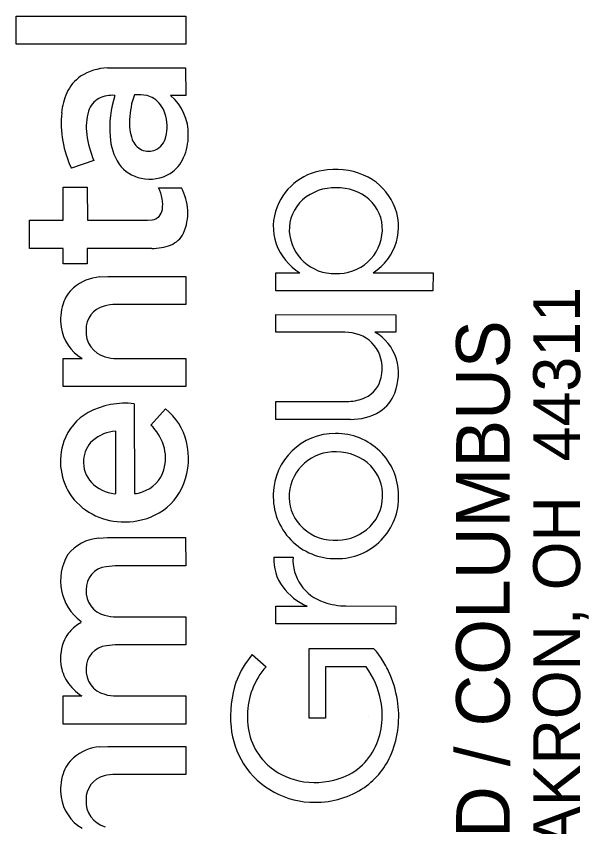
# Model space of a CAD drawing. Extents: x -1.6 to 34, y 0 to 22.
# Drawn here: x 32.376 to 32.984, y 3.882 to 4.744 of the extents above; entities that cross this region are included whole.
import ezdxf

# ---------------------------------------------------------------- set-up
doc = ezdxf.new("R2010")
doc.units = 0
doc.layers.add('SH_Data', color=7, linetype='Continuous')

msp = doc.modelspace()

# ---------------------------------------------------------------- linework, layer by layer
at = {"layer": 'SH_Data'}
for p, q in [((32.37557, 4.71411), (32.37557, 4.74397)), ((32.37557, 4.74397), (32.55571, 4.74397)), ((32.55571, 4.74397), (32.55571, 4.71411)), ((32.55571, 4.71411), (32.37557, 4.71411)), ((32.47265, 4.68899), (32.55553, 4.68918)), ((32.55553, 4.68918), (32.55571, 4.65956)), ((32.55571, 4.65956), (32.53971, 4.65956)), ((32.45818, 4.59045), (32.43431, 4.58233)), ((32.42542, 4.52705), (32.42548, 4.56209)), ((32.42548, 4.56209), (32.45108, 4.56209)), ((32.45108, 4.56209), (32.45117, 4.52705)), ((32.52695, 4.56159), (32.5511, 4.56159)), ((32.38964, 4.52701), (32.42542, 4.52705)), ((32.38964, 4.49719), (32.38964, 4.52701)), ((32.45117, 4.52705), (32.51498, 4.52705)), ((32.51498, 4.52705), (32.52005, 4.52749)), ((32.42542, 4.49717), (32.38964, 4.49719)), ((32.42542, 4.48067), (32.42542, 4.49717)), ((32.51969, 4.49718), (32.45108, 4.49715)), ((32.45108, 4.49715), (32.45108, 4.48066)), ((32.45108, 4.48066), (32.42542, 4.48067)), ((32.46439, 4.46686), (32.47289, 4.46732)), ((32.47289, 4.46732), (32.55571, 4.46732)), ((32.55571, 4.46732), (32.55571, 4.43753)), ((32.65152, 4.47113), (32.67709, 4.47115)), ((32.65152, 4.45215), (32.65152, 4.47113)), ((32.75491, 4.47132), (32.81858, 4.47108)), ((32.81858, 4.47108), (32.81843, 4.45215)), ((32.81843, 4.45215), (32.65152, 4.45215)), ((32.55571, 4.43753), (32.4814, 4.43746)), ((32.65152, 4.40801), (32.65153, 4.42672)), ((32.65153, 4.42672), (32.7791, 4.42664)), ((32.7791, 4.42664), (32.77908, 4.40796)), ((32.7249, 4.40796), (32.65152, 4.40801)), ((32.7328, 4.40727), (32.7249, 4.40796)), ((32.77908, 4.40796), (32.75689, 4.40796)), ((32.42542, 4.38016), (32.44552, 4.38021)), ((32.42542, 4.35035), (32.42542, 4.38016)), ((32.48222, 4.38021), (32.55569, 4.38021)), ((32.55569, 4.38021), (32.55571, 4.35045)), ((32.55571, 4.35045), (32.42542, 4.35035)), ((32.65154, 4.33443), (32.72905, 4.3345)), ((32.65165, 4.31543), (32.65154, 4.33443)), ((32.50108, 4.33209), (32.50118, 4.23657)), ((32.51882, 4.30927), (32.53422, 4.32662)), ((32.73073, 4.31543), (32.65165, 4.31543)), ((32.48144, 4.23644), (32.48144, 4.30296)), ((32.48016, 4.23628), (32.48144, 4.23644)), ((32.46329, 4.18915), (32.47259, 4.18968)), ((32.47259, 4.18968), (32.55557, 4.18968)), ((32.55557, 4.18968), (32.55571, 4.15982)), ((32.64932, 4.16907), (32.66978, 4.16907)), ((32.48058, 4.15981), (32.47102, 4.15881)), ((32.55571, 4.15982), (32.48058, 4.15981)), ((32.65152, 4.11699), (32.68476, 4.117)), ((32.65152, 4.098), (32.65152, 4.11699)), ((32.72605, 4.11703), (32.7791, 4.11696)), ((32.7791, 4.11696), (32.77903, 4.098)), ((32.48218, 4.10553), (32.55571, 4.10548)), ((32.55571, 4.10548), (32.55571, 4.07568)), ((32.44443, 4.09922), (32.44455, 4.10072)), ((32.77903, 4.098), (32.65152, 4.098)), ((32.4809, 4.07567), (32.47143, 4.07474)), ((32.55571, 4.07568), (32.4809, 4.07567)), ((32.6868, 4.07185), (32.75516, 4.07192)), ((32.6868, 3.99778), (32.6868, 4.07185)), ((32.62636, 4.06548), (32.64114, 4.05241)), ((32.70448, 4.05241), (32.70432, 3.99775)), ((32.74737, 4.05227), (32.70448, 4.05241)), ((32.42542, 3.99152), (32.42545, 4.02138)), ((32.42545, 4.02138), (32.44515, 4.02138)), ((32.48206, 4.02138), (32.55571, 4.02136)), ((32.55571, 4.02136), (32.55571, 3.99156)), ((32.75, 4), (32.75, 4)), ((32.55571, 3.99156), (32.42542, 3.99152)), ((32.70432, 3.99775), (32.6868, 3.99778)), ((32.46439, 3.96736), (32.47289, 3.96783)), ((32.47289, 3.96783), (32.55571, 3.96783)), ((32.55571, 3.96783), (32.55571, 3.93804)), ((32.55571, 3.93804), (32.4814, 3.93796))]:
    msp.add_line(p, q, dxfattribs=at)
msp.add_lwpolyline([(32.37557, 4.71411), (32.37557, 4.74397), (32.55571, 4.74397), (32.55571, 4.71411)], close=True, dxfattribs=at)
for points in [[(32.47265, 4.68899), (32.55553, 4.68918), (32.55571, 4.65956)], [(32.55571, 4.65956), (32.53971, 4.65956)], [(32.45818, 4.59045), (32.43431, 4.58233)], [(32.51969, 4.49718), (32.45108, 4.49715), (32.45108, 4.48066), (32.42542, 4.48067), (32.42542, 4.49717), (32.38964, 4.49719), (32.38964, 4.52701), (32.42542, 4.52705), (32.42548, 4.56209), (32.45108, 4.56209), (32.45117, 4.52705), (32.51498, 4.52705), (32.52005, 4.52749)], [(32.52695, 4.56159), (32.5511, 4.56159)], [(32.46439, 4.46686), (32.47289, 4.46732), (32.55571, 4.46732), (32.55571, 4.43753), (32.4814, 4.43746)], [(32.75491, 4.47132), (32.81858, 4.47108), (32.81843, 4.45215), (32.65152, 4.45215)], [(32.65152, 4.45215), (32.65152, 4.47113), (32.67709, 4.47115)], [(32.7328, 4.40727), (32.7249, 4.40796), (32.65152, 4.40801), (32.65153, 4.42672), (32.7791, 4.42664), (32.77908, 4.40796), (32.75689, 4.40796)], [(32.42542, 4.35035), (32.42542, 4.38016), (32.44552, 4.38021)], [(32.48222, 4.38021), (32.55569, 4.38021), (32.55571, 4.35045), (32.42542, 4.35035)], [(32.73073, 4.31543), (32.65165, 4.31543), (32.65154, 4.33443), (32.72905, 4.3345)], [(32.50108, 4.33209), (32.50118, 4.23657)], [(32.51882, 4.30927), (32.53422, 4.32662)], [(32.48016, 4.23628), (32.48144, 4.23644), (32.48144, 4.30296)], [(32.46329, 4.18915), (32.47259, 4.18968), (32.55557, 4.18968), (32.55571, 4.15982), (32.48058, 4.15981), (32.47102, 4.15881)], [(32.64932, 4.16907), (32.66978, 4.16907)], [(32.72605, 4.11703), (32.7791, 4.11696), (32.77903, 4.098), (32.65152, 4.098)], [(32.65152, 4.098), (32.65152, 4.11699), (32.68476, 4.117)], [(32.48218, 4.10553), (32.55571, 4.10548), (32.55571, 4.07568), (32.4809, 4.07567), (32.47143, 4.07474)], [(32.44443, 4.09922), (32.44455, 4.10072)], [(32.74737, 4.05227), (32.70448, 4.05241), (32.70432, 3.99775), (32.6868, 3.99778), (32.6868, 4.07185), (32.75516, 4.07192)], [(32.62636, 4.06548), (32.64114, 4.05241)], [(32.42542, 3.99152), (32.42545, 4.02138), (32.44515, 4.02138)], [(32.48206, 4.02138), (32.55571, 4.02136), (32.55571, 3.99156), (32.42542, 3.99152)], [(32.46439, 3.96736), (32.47289, 3.96783), (32.55571, 3.96783), (32.55571, 3.93804), (32.4814, 3.93796)]]:
    msp.add_lwpolyline(points, dxfattribs=at)
for centre, radius, start, end in [((32.47452, 4.63256), 0.05646, 91.89422, 122.63175), ((32.47452, 4.63256), 0.05646, 91.89422, 122.63175), ((32.46847, 4.64467), 0.04302, 124.53704, 155.65938), ((32.46847, 4.64467), 0.04302, 124.53704, 155.65938), ((32.48824, 4.63612), 0.06457, 155.9764, 175.31491), ((32.48824, 4.63612), 0.06457, 155.9764, 175.31491), ((32.47525, 4.6356), 0.024, 119.42515, 161.66285), ((32.47525, 4.6356), 0.024, 119.42515, 161.66285), ((32.47786, 4.62778), 0.03213, 85.38017, 116.62224), ((32.47786, 4.62778), 0.03213, 85.38017, 116.62224), ((32.58787, 4.62508), 0.1129, 162.08213, 184.52847), ((32.58787, 4.62508), 0.1129, 162.08213, 184.52847), ((32.58013, 4.63131), 0.08411, 159.83657, 178.03621), ((32.58013, 4.63131), 0.08411, 159.83657, 178.03621), ((32.50509, 4.60743), 0.05302, 79.66963, 94.23216), ((32.50509, 4.60743), 0.05302, 79.66963, 94.23216), ((32.50892, 4.63643), 0.02384, 56.89129, 76.21489), ((32.50892, 4.63643), 0.02384, 56.89129, 76.21489), ((32.5052, 4.63184), 0.02973, 17.59837, 55.72819), ((32.5052, 4.63184), 0.02973, 17.59837, 55.72819), ((32.50551, 4.61914), 0.05295, 358.07459, 49.76196), ((32.50551, 4.61914), 0.05295, 358.07459, 49.76196), ((32.53639, 4.63078), 0.113, 174.61011, 205.38987), ((32.53639, 4.63078), 0.113, 174.61011, 205.38987), ((32.50758, 4.62645), 0.05758, 163.13694, 188.16749), ((32.50758, 4.62645), 0.05758, 163.13694, 188.16749), ((32.4916, 4.6264), 0.04435, 345.94084, 18.99188), ((32.4916, 4.6264), 0.04435, 345.94084, 18.99188), ((32.54655, 4.6303), 0.05063, 175.59026, 199.88569), ((32.54655, 4.6303), 0.05063, 175.59026, 199.88569), ((32.54725, 4.62973), 0.09735, 186.75982, 203.79807), ((32.54725, 4.62973), 0.09735, 186.75982, 203.79807), ((32.53279, 4.61874), 0.05752, 182.56764, 213.71437), ((32.53279, 4.61874), 0.05752, 182.56764, 213.71437), ((32.51642, 4.61886), 0.01841, 198.28436, 293.30806), ((32.51642, 4.61886), 0.01841, 198.28436, 293.30806), ((32.51521, 4.61994), 0.01989, 295.28829, 347.46387), ((32.51521, 4.61994), 0.01989, 295.28829, 347.46387), ((32.50187, 4.61678), 0.05657, 336.01604, 0.59505), ((32.50187, 4.61678), 0.05657, 336.01604, 0.59505), ((32.51752, 4.60969), 0.03938, 303.44357, 336.18), ((32.51752, 4.60969), 0.03938, 303.44357, 336.18), ((32.51487, 4.60782), 0.03656, 215.06685, 259.81327), ((32.51487, 4.60782), 0.03656, 215.06685, 259.81327), ((32.51753, 4.6131), 0.04227, 257.52557, 300.88195), ((32.51753, 4.6131), 0.04227, 257.52557, 300.88195), ((32.71081, 4.51825), 0.06243, 93.98662, 158.31194), ((32.71081, 4.51825), 0.06243, 93.98662, 158.31194), ((32.71557, 4.5065), 0.07459, 62.68889, 97.01346), ((32.71557, 4.5065), 0.07459, 62.68889, 97.01346), ((32.72123, 4.51914), 0.06076, 25.06574, 61.96022), ((32.72123, 4.51914), 0.06076, 25.06574, 61.96022), ((32.48625, 4.54199), 0.04518, 10.15449, 25.72303), ((32.48625, 4.54199), 0.04518, 10.15449, 25.72303), ((32.50302, 4.53506), 0.05491, 336.58903, 28.89913), ((32.50302, 4.53506), 0.05491, 336.58903, 28.89913), ((32.71379, 4.51017), 0.05134, 87.89653, 131.18123), ((32.71379, 4.51017), 0.05134, 87.89653, 131.18123), ((32.7175, 4.51023), 0.05127, 49.90886, 92.03625), ((32.7175, 4.51023), 0.05127, 49.90886, 92.03625), ((32.49573, 4.54365), 0.03556, 351.91398, 10.20594), ((32.49573, 4.54365), 0.03556, 351.91398, 10.20594), ((32.70695, 4.52016), 0.05815, 158.65601, 198.17101), ((32.70695, 4.52016), 0.05815, 158.65601, 198.17101), ((32.7092, 4.51674), 0.04338, 132.32887, 182.09489), ((32.7092, 4.51674), 0.04338, 132.32887, 182.09489), ((32.72154, 4.51733), 0.04327, 358.04871, 47.94467), ((32.72154, 4.51733), 0.04327, 358.04871, 47.94467), ((32.7245, 4.52004), 0.05743, 301.97764, 25.64176), ((32.7245, 4.52004), 0.05743, 301.97764, 25.64176), ((32.51837, 4.54001), 0.01263, 277.61423, 353.79181), ((32.51837, 4.54001), 0.01263, 277.61423, 353.79181), ((32.71352, 4.51815), 0.04776, 183.59741, 271.7045), ((32.71352, 4.51815), 0.04776, 183.59741, 271.7045), ((32.71717, 4.51801), 0.04766, 267.31494, 357.4019), ((32.71717, 4.51801), 0.04766, 267.31494, 357.4019), ((32.52913, 4.52612), 0.02749, 292.68889, 332.05977), ((32.52913, 4.52612), 0.02749, 292.68889, 332.05977), ((32.52088, 4.54856), 0.05139, 268.67266, 291.52354), ((32.52088, 4.54856), 0.05139, 268.67266, 291.52354), ((32.7103, 4.52433), 0.0627, 200.83985, 238.01619), ((32.7103, 4.52433), 0.0627, 200.83985, 238.01619), ((32.46871, 4.41716), 0.04988, 94.97056, 130.22484), ((32.46871, 4.41716), 0.04988, 94.97056, 130.22484), ((32.46348, 4.42551), 0.04016, 132.22383, 161.68229), ((32.46348, 4.42551), 0.04016, 132.22383, 161.68229), ((32.47872, 4.42108), 0.05602, 162.27398, 187.79173), ((32.47872, 4.42108), 0.05602, 162.27398, 187.79173), ((32.48108, 4.39145), 0.04601, 89.60515, 105.33026), ((32.48108, 4.39145), 0.04601, 89.60515, 105.33026), ((32.47482, 4.41155), 0.02498, 103.68683, 182.21395), ((32.47482, 4.41155), 0.02498, 103.68683, 182.21395), ((32.47027, 4.4209), 0.04763, 188.96462, 238.69865), ((32.47027, 4.4209), 0.04763, 188.96462, 238.69865), ((32.47735, 4.40846), 0.02757, 175.58441, 255.13816), ((32.47735, 4.40846), 0.02757, 175.58441, 255.13816), ((32.72711, 4.36998), 0.03772, 33.50082, 81.32954), ((32.72711, 4.36998), 0.03772, 33.50082, 81.32954), ((32.73239, 4.36485), 0.04959, 17.62209, 60.38974), ((32.73239, 4.36485), 0.04959, 17.62209, 60.38974), ((32.72414, 4.3695), 0.04048, 346.56179, 31.75389), ((32.72414, 4.3695), 0.04048, 346.56179, 31.75389), ((32.48183, 4.42235), 0.04215, 254.08913, 270.52838), ((32.48183, 4.42235), 0.04215, 254.08913, 270.52838), ((32.72343, 4.36415), 0.05838, 339.16197, 15.61485), ((32.72343, 4.36415), 0.05838, 339.16197, 15.61485), ((32.73371, 4.36616), 0.03042, 294.63214, 348.48625), ((32.73371, 4.36616), 0.03042, 294.63214, 348.48625), ((32.739, 4.35901), 0.04201, 303.10391, 338.15613), ((32.739, 4.35901), 0.04201, 303.10391, 338.15613), ((32.72747, 4.38081), 0.04633, 271.95199, 294.08943), ((32.72747, 4.38081), 0.04633, 271.95199, 294.08943), ((32.49176, 4.24874), 0.08387, 83.62118, 118.28448), ((32.49176, 4.24874), 0.08387, 83.62118, 118.28448), ((32.49399, 4.2763), 0.06443, 13.53275, 51.36266), ((32.49399, 4.2763), 0.06443, 13.53275, 51.36266), ((32.47894, 4.27368), 0.05583, 118.82935, 160.62242), ((32.47894, 4.27368), 0.05583, 118.82935, 160.62242), ((32.7321, 4.37256), 0.05715, 268.62699, 301.47779), ((32.7321, 4.37256), 0.05715, 268.62699, 301.47779), ((32.48033, 4.27018), 0.05485, 19.0387, 45.44322), ((32.48033, 4.27018), 0.05485, 19.0387, 45.44322), ((32.4844, 4.26071), 0.04236, 94.01311, 130.88062), ((32.4844, 4.26071), 0.04236, 94.01311, 130.88062), ((32.71435, 4.23484), 0.06552, 89.48213, 178.77752), ((32.71435, 4.23484), 0.06552, 89.48213, 178.77752), ((32.71582, 4.23414), 0.06623, 0.42265, 90.7613), ((32.71582, 4.23414), 0.06623, 0.42265, 90.7613), ((32.48697, 4.27074), 0.06438, 160.52138, 215.78155), ((32.48697, 4.27074), 0.06438, 160.52138, 215.78155), ((32.47703, 4.2709), 0.02985, 132.98553, 177.1802), ((32.47703, 4.2709), 0.02985, 132.98553, 177.1802), ((32.48289, 4.27384), 0.0758, 339.35431, 13.37708), ((32.48289, 4.27384), 0.0758, 339.35431, 13.37708), ((32.48724, 4.27433), 0.04701, 344.60723, 17.00675), ((32.48724, 4.27433), 0.04701, 344.60723, 17.00675), ((32.71397, 4.23244), 0.04846, 87.68827, 175.01696), ((32.71397, 4.23244), 0.04846, 87.68827, 175.01696), ((32.71659, 4.23036), 0.05052, 44.91202, 90.75914), ((32.71659, 4.23036), 0.05052, 44.91202, 90.75914), ((32.47824, 4.26966), 0.03114, 175.00138, 223.2876), ((32.47824, 4.26966), 0.03114, 175.00138, 223.2876), ((32.71955, 4.23452), 0.04549, 358.32279, 43.83486), ((32.71955, 4.23452), 0.04549, 358.32279, 43.83486), ((32.49895, 4.27177), 0.03504, 288.01084, 343.55364), ((32.49895, 4.27177), 0.03504, 288.01084, 343.55364), ((32.48546, 4.27826), 0.04232, 225.06454, 262.79701), ((32.48546, 4.27826), 0.04232, 225.06454, 262.79701), ((32.49548, 4.26982), 0.0626, 300.94393, 338.73223), ((32.49548, 4.26982), 0.0626, 300.94393, 338.73223), ((32.48908, 4.27516), 0.06872, 217.74341, 271.65606), ((32.48908, 4.27516), 0.06872, 217.74341, 271.65606), ((32.50129, 4.25678), 0.02021, 269.70042, 294.87295), ((32.50129, 4.25678), 0.02021, 269.70042, 294.87295), ((32.71483, 4.2334), 0.06606, 177.53728, 270.94524), ((32.71483, 4.2334), 0.06606, 177.53728, 270.94524), ((32.71085, 4.23311), 0.0453, 175.51467, 221.42047), ((32.71085, 4.23311), 0.0453, 175.51467, 221.42047), ((32.71671, 4.23271), 0.06536, 269.30834, 1.67905), ((32.71671, 4.23271), 0.06536, 269.30834, 1.67905), ((32.71931, 4.23374), 0.04572, 308.90382, 359.30947), ((32.71931, 4.23374), 0.04572, 308.90382, 359.30947), ((32.49204, 4.27702), 0.07055, 269.20529, 300.33566), ((32.49204, 4.27702), 0.07055, 269.20529, 300.33566), ((32.71399, 4.23734), 0.05046, 222.66255, 268.37331), ((32.71399, 4.23734), 0.05046, 222.66255, 268.37331), ((32.71567, 4.23859), 0.05178, 266.55312, 308.67253), ((32.71567, 4.23859), 0.05178, 266.55312, 308.67253), ((32.46638, 4.14404), 0.04521, 93.91118, 142.30723), ((32.46638, 4.14404), 0.04521, 93.91118, 142.30723), ((32.47585, 4.14373), 0.05319, 148.28793, 233.9556), ((32.47585, 4.14373), 0.05319, 148.28793, 233.9556), ((32.69878, 4.16662), 0.04952, 177.16211, 216.28024), ((32.69878, 4.16662), 0.04952, 177.16211, 216.28024), ((32.71735, 4.16638), 0.04764, 176.76988, 252.15044), ((32.71735, 4.16638), 0.04764, 176.76988, 252.15044), ((32.47384, 4.13499), 0.02399, 96.75763, 181.6251), ((32.47384, 4.13499), 0.02399, 96.75763, 181.6251), ((32.70975, 4.17555), 0.06366, 216.91526, 246.88619), ((32.70975, 4.17555), 0.06366, 216.91526, 246.88619), ((32.47577, 4.13241), 0.02597, 175.81573, 256.16716), ((32.47577, 4.13241), 0.02597, 175.81573, 256.16716), ((32.7269, 4.19175), 0.07473, 251.13884, 269.34694), ((32.7269, 4.19175), 0.07473, 251.13884, 269.34694), ((32.4817, 4.15053), 0.04501, 254.34629, 270.61033), ((32.4817, 4.15053), 0.04501, 254.34629, 270.61033), ((32.4638, 4.06267), 0.04137, 117.91625, 139.24296), ((32.4638, 4.06267), 0.04137, 117.91625, 139.24296), ((32.46194, 4.06452), 0.03875, 139.52447, 154.84698), ((32.46194, 4.06452), 0.03875, 139.52447, 154.84698), ((32.47144, 4.0612), 0.04877, 156.06382, 187.3493), ((32.47144, 4.0612), 0.04877, 156.06382, 187.3493), ((32.47421, 4.05056), 0.02434, 96.5532, 179.94902), ((32.47421, 4.05056), 0.02434, 96.5532, 179.94902), ((32.72498, 4.03937), 0.04438, 30.98913, 47.16099), ((32.72498, 4.03937), 0.04438, 30.98913, 47.16099), ((32.70163, 4.00187), 0.09855, 139.79476, 159.13696), ((32.70163, 4.00187), 0.09855, 139.79476, 159.13696), ((32.67091, 4.00018), 0.11106, 25.30315, 33.96179), ((32.67091, 4.00018), 0.11106, 25.30315, 33.96179), ((32.46461, 4.05974), 0.04181, 186.5579, 213.38846), ((32.46461, 4.05974), 0.04181, 186.5579, 213.38846), ((32.47608, 4.04863), 0.02628, 175.722, 255.78627), ((32.47608, 4.04863), 0.02628, 175.722, 255.78627), ((32.69899, 4.00079), 0.07753, 138.25804, 179.70064), ((32.69899, 4.00079), 0.07753, 138.25804, 179.70064), ((32.67889, 4.00099), 0.08556, 10.07509, 36.83189), ((32.67889, 4.00099), 0.08556, 10.07509, 36.83189), ((32.6704, 3.99987), 0.11166, 8.80339, 25.33484), ((32.6704, 3.99987), 0.11166, 8.80339, 25.33484), ((32.47886, 4.07078), 0.0598, 214.70433, 235.68724), ((32.47886, 4.07078), 0.0598, 214.70433, 235.68724), ((32.7187, 3.99968), 0.11536, 161.14379, 185.62812), ((32.7187, 3.99968), 0.11536, 161.14379, 185.62812), ((32.48195, 4.06518), 0.0438, 253.66719, 270.14979), ((32.48195, 4.06518), 0.0438, 253.66719, 270.14979), ((32.68425, 4.00057), 0.08036, 333.46689, 11.03668), ((32.68425, 4.00057), 0.08036, 333.46689, 11.03668), ((32.67564, 3.99977), 0.10649, 338.28866, 9.28548), ((32.67564, 3.99977), 0.10649, 338.28866, 9.28548), ((32.68811, 3.99732), 0.06676, 176.66577, 223.6912), ((32.68811, 3.99732), 0.06676, 176.66577, 223.6912), ((32.69336, 3.99699), 0.08987, 185.50773, 212.01294), ((32.69336, 3.99699), 0.08987, 185.50773, 212.01294), ((32.46871, 3.91767), 0.04988, 94.97056, 130.22484), ((32.46871, 3.91767), 0.04988, 94.97056, 130.22484), ((32.69868, 3.99547), 0.0652, 282.88151, 331.81475), ((32.69868, 3.99547), 0.0652, 282.88151, 331.81475), ((32.46348, 3.92602), 0.04016, 132.22383, 161.68229), ((32.46348, 3.92602), 0.04016, 132.22383, 161.68229), ((32.69835, 3.99168), 0.08241, 305.03061, 337.67573), ((32.69835, 3.99168), 0.08241, 305.03061, 337.67573), ((32.69211, 3.99748), 0.08908, 212.70222, 270.71399), ((32.69211, 3.99748), 0.08908, 212.70222, 270.71399), ((32.69045, 4.00011), 0.07039, 224.02147, 253.88), ((32.69045, 4.00011), 0.07039, 224.02147, 253.88), ((32.47872, 3.92158), 0.05602, 162.27398, 187.79173), ((32.47872, 3.92158), 0.05602, 162.27398, 187.79173), ((32.48108, 3.89196), 0.04601, 89.60515, 105.33026), ((32.48108, 3.89196), 0.04601, 89.60515, 105.33026), ((32.47482, 3.91206), 0.02498, 103.68683, 182.21395), ((32.47482, 3.91206), 0.02498, 103.68683, 182.21395), ((32.69318, 4.01254), 0.08309, 254.45353, 283.9512), ((32.69318, 4.01254), 0.08309, 254.45353, 283.9512), ((32.69429, 3.99979), 0.09138, 269.3273, 304.19632), ((32.69429, 3.99979), 0.09138, 269.3273, 304.19632), ((32.47027, 3.92141), 0.04763, 188.96462, 238.69865), ((32.47027, 3.92141), 0.04763, 188.96462, 238.69865), ((32.47735, 3.90897), 0.02757, 175.58441, 255.13816), ((32.47735, 3.90897), 0.02757, 175.58441, 255.13816)]:
    msp.add_arc(centre, radius, start, end, dxfattribs=at)

# ---------------------------------------------------------------- texts
for s, height, p in [('450 GRANT ST., AKRON, OH  44311', 0.0498462, (32.97489, 3.33738)), ('AKRON / CLEVELAND / COLUMBUS', 0.056969, (32.90012, 3.138))]:
    msp.add_text(s, height=height, rotation=90, dxfattribs=at).set_placement(p)

doc.saveas('drawing.dxf')
